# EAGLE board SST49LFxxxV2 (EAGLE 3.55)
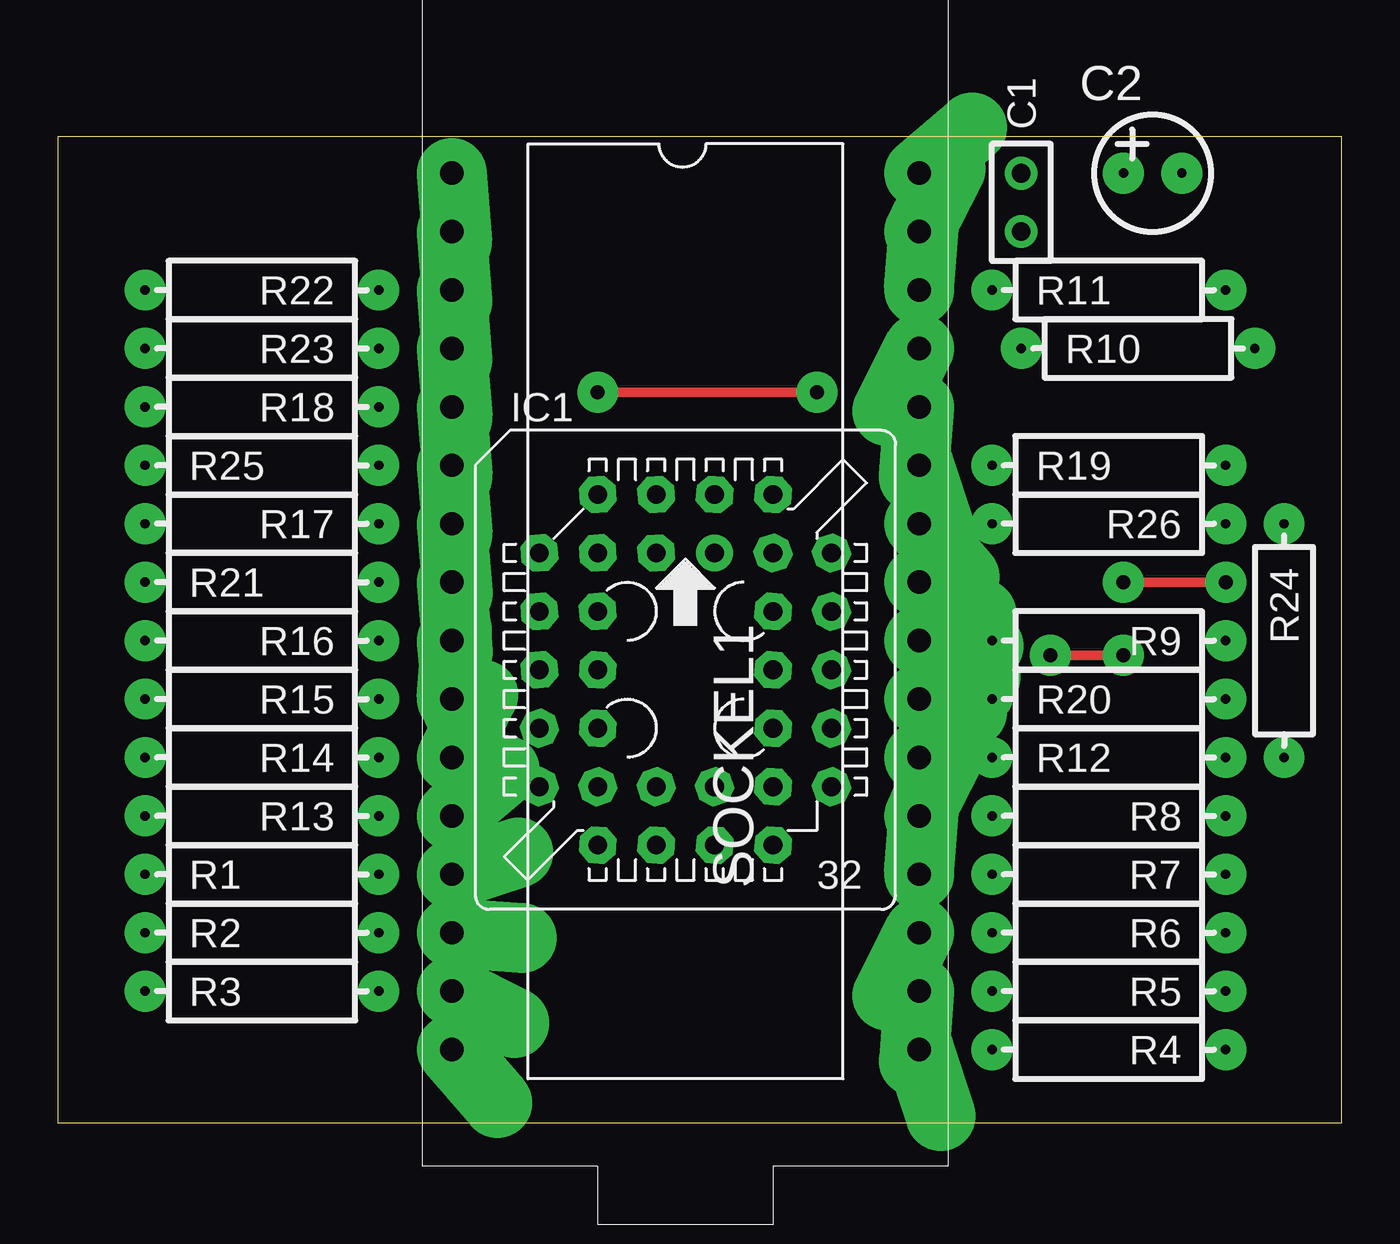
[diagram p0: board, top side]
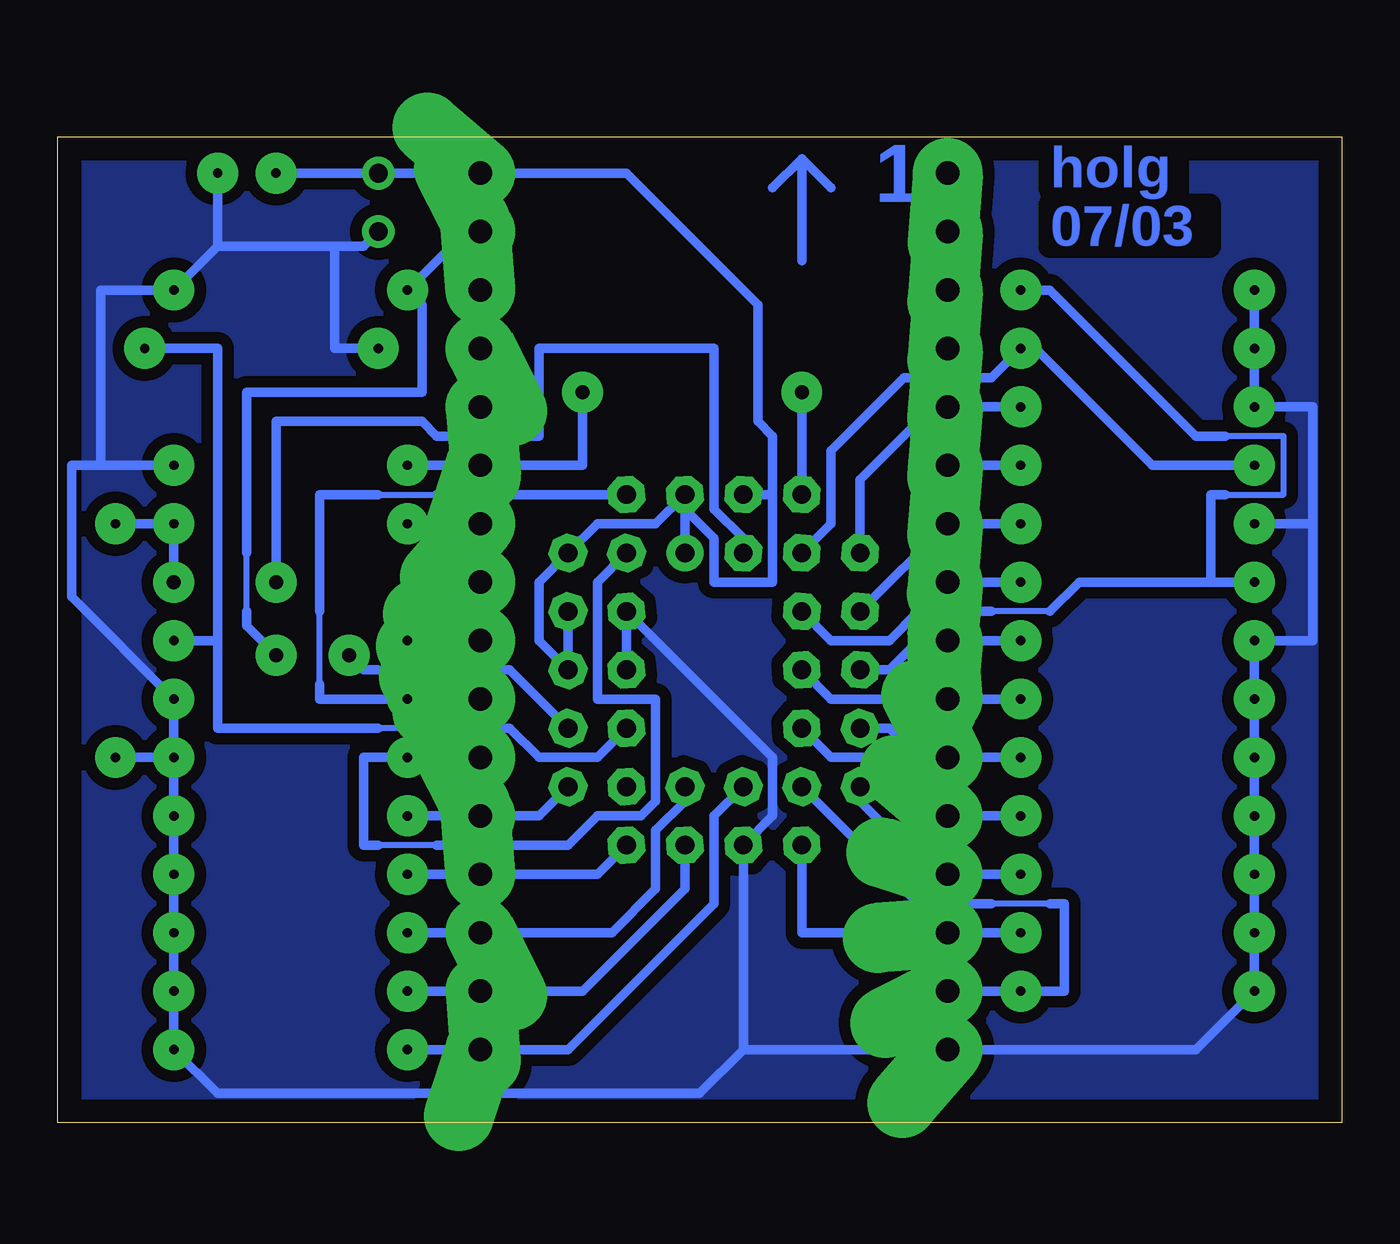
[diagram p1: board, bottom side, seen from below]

Size 55.86 x 42.85 mm. Coordinates in mm from the lower left corner, seen from the top.
Outline: 0,0 55.86,0 55.86,42.85 0,42.85 0,0
Copper layers used: Top, Bottom

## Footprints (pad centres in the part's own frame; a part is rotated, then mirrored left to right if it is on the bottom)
RM2,5 = drill 0.813 pad 1.422 round:  0,0;  2.54,0
KO01 = drill 0.406 pad 1.778 round:  -1.27,0;  1.27,0
C32 = drill 0.813 pad 1.6 round:  1.27,5.08 | drill 0.813 pad 1.6 octagon:  -1.27,7.62;  -1.27,5.08;  -3.81,7.62;  -6.35,5.08;  -3.81,5.08;  -6.35,2.54;  -3.81,2.54;  -6.35,0;  -3.81,0;  -6.35,-2.54;  -3.81,-2.54;  -6.35,-5.08;  -3.81,-7.62;  -3.81,-5.08;  -1.27,-7.62;  -1.27,-5.08;  1.27,-7.62;  1.27,-5.08;  3.81,-7.62;  6.35,-5.08;  3.81,-5.08;  6.35,-2.54;  3.81,-2.54;  6.35,0;  3.81,0;  6.35,2.54;  3.81,2.54;  6.35,5.08;  3.81,7.62;  3.81,5.08;  1.27,7.62
S04 = drill 0.406 pad 1.778 round:  -5.08,0;  5.08,0
AOV32 = drill 1.016 pad 3.048 offset:  -19.05,-10.16;  -16.51,-10.16;  -3.81,-10.16;  -1.27,-10.16;  -13.97,-10.16;  -11.43,-10.16;  -6.35,-10.16;  -8.89,-10.16;  1.27,-10.16;  3.81,-10.16;  6.35,-10.16;  8.89,-10.16;  11.43,-10.16;  13.97,-10.16;  16.51,-10.16;  19.05,-10.16;  19.05,10.16;  16.51,10.16;  13.97,10.16;  11.43,10.16;  8.89,10.16;  6.35,10.16;  3.81,10.16;  1.27,10.16;  -1.27,10.16;  -3.81,10.16;  -6.35,10.16;  -8.89,10.16;  -11.43,10.16;  -13.97,10.16;  -16.51,10.16;  -19.05,10.16

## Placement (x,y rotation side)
C1  C100NK  [RM2,5]  41.91,38.73 90 top
C2  4u7  [KO01]  47.62,41.27 0 top
IC1  SST49LFXXX  [C32]  27.3,19.68 0 top
R1  5k6  [S04]  8.89,10.79 0 top
R2  5k6  [S04]  8.89,8.26 0 top
R3  5k6  [S04]  8.89,5.71 0 top
R4  5k6  [S04]  45.72,3.17 180 top
R5  5k6  [S04]  45.72,5.71 180 top
R6  5k6  [S04]  45.72,8.26 180 top
R7  5k6  [S04]  45.72,10.79 180 top
R8  5k6  [S04]  45.72,13.34 180 top
R9  3k3  [S04]  45.72,20.95 180 top
R10  10k  [S04]  46.99,33.66 0 top
R11  2k7  [S04]  45.72,36.2 0 top
R12  2k7  [S04]  45.72,15.88 0 top
R13  2k7  [S04]  8.89,13.34 180 top
R14  2k7  [S04]  8.89,15.88 180 top
R15  2k7  [S04]  8.89,18.41 180 top
R16  2k7  [S04]  8.89,20.95 180 top
R17  2k7  [S04]  8.89,26.04 180 top
R18  2k7  [S04]  8.89,31.11 180 top
R19  2k7  [S04]  45.72,28.57 0 top
R20  2k7  [S04]  45.72,18.41 0 top
R21  3k3  [S04]  8.89,23.5 0 top
R22  10k  [S04]  8.89,36.2 180 top
R23  10k  [S04]  8.89,33.66 180 top
R24  10k  [S04]  53.34,20.95 270 top
R25  3k3  [S04]  8.89,28.57 0 top
R26  3k3  [S04]  45.72,26.04 180 top
SOCKEL1  Sockel1  [AOV32]  27.3,22.23 270 top

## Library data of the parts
C1 = holgnorm
C2 R1-R26 = holg_plt
IC1 = ic_holg
SOCKEL1 = galeprom

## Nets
/CE: IC1. R12. SOCKEL1.
/OE: R9. SOCKEL1.
/WR: IC1. R11. SOCKEL1.
A0: IC1. R13. SOCKEL1.
A1: IC1. R14. SOCKEL1.
A2: IC1. R15. SOCKEL1.
A3: IC1. R16. SOCKEL1.
A4: R21. SOCKEL1.
A4B: IC1. R21. R22.
A5: IC1. R17. SOCKEL1.
A6: R25. SOCKEL1.
A6B: IC1. R23. R25.
A7: IC1. R18. SOCKEL1.
A8: IC1. R19. SOCKEL1.
A9: R26. SOCKEL1.
A9B: IC1. R24. R26.
A10: IC1. R20. SOCKEL1.
D0: IC1. R1. SOCKEL1.
D1: IC1. R2. SOCKEL1.
D2: IC1. R3. SOCKEL1.
D3: IC1. R4. SOCKEL1.
D4: IC1. R5. SOCKEL1.
D5: IC1. R6. SOCKEL1.
D6: IC1. R7. SOCKEL1.
D7: IC1. R8. SOCKEL1.
GND: C1. C2. IC1. R1. R2. R3. R4. R5. R6. R7. R8. R10. R11. R12. R13. R14. R15. R16. R17. R18. R19. R20. R22. R23. R24. SOCKEL1.
N$1: C1. C2. IC1. SOCKEL1.
N$5: IC1. R9. R10.

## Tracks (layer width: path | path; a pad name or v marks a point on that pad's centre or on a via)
/CE
  Bottom 0.254: 39.37,12.06 41.91,12.06
  Bottom 0.406: 31.11,24.77 32.38,23.5 32.38,18.41 29.84,18.41 29.84,13.97 30.48,13.34 32.38,13.34 33.66,12.06 39.37,12.06 | 37.47,15.88 40.64,15.88 42.55,15.88 42.55,12.06 41.91,12.06
/OE
  Bottom 0.406: 37.47,20.95 R9.
/WR  (via drill 0.61 pad 1.78)
  Top 0.406: v43.18,20.32 v46.35,20.32
  Bottom 0.254: 47.62,22.23 47.62,24.77 | 39.37,19.68 41.91,19.68
  Bottom 0.406: 33.66,17.14 36.2,19.68 39.37,19.68 | v43.18,20.32 42.55,19.68 41.91,19.68 | 37.47,38.73 38.1,38.73 40.64,36.2 40.01,35.56 40.01,31.75 47.62,31.75 47.62,24.77 | 47.62,22.23 47.62,21.59 v46.35,20.32
A0
  Bottom 0.406: 13.97,13.34 17.14,13.34 17.78,13.34 20.32,15.88 22.23,15.88 23.5,17.14
A1
  Bottom 0.406: 13.97,15.88 17.14,15.88 18.41,15.88 19.68,17.14 20.95,17.14
A2
  Bottom 0.406: 23.5,19.68 22.23,18.41 17.14,18.41 13.97,18.41
A3
  Bottom 0.406: 13.97,20.95 17.14,20.95 18.41,20.95 19.68,19.68 20.95,19.68
A4
  Bottom 0.406: R21. 17.14,23.5
A4B
  Bottom 0.254: 5.08,29.84 2.54,29.84 2.54,27.3 5.08,27.3 | 12.7,22.23 15.24,22.23
  Bottom 0.406: 3.81,23.5 5.71,23.5 | 23.5,22.23 22.23,20.95 19.68,20.95 18.41,22.23 15.24,22.23 | 5.71,23.5 11.43,23.5 12.7,22.23 | 5.71,23.5 5.71,27.3 5.08,27.3 | 13.97,36.2 12.7,36.2 6.35,29.84 5.08,29.84
A5
  Bottom 0.406: 20.95,22.23 17.14,26.04 13.97,26.04
A6
  Bottom 0.406: R25. 17.14,28.57
A6B
  Bottom 0.406: 23.5,24.77 22.23,26.04 22.23,29.21 19.05,32.38 15.24,32.38 13.97,33.66 13.34,33.66 8.26,28.57 3.81,28.57
A7
  Bottom 0.406: 20.95,24.77 20.95,27.94 17.78,31.11 17.14,31.11 13.97,31.11
A8  (via drill 0.61 pad 1.78)
  Top 0.406: v23.5,31.75 v33.02,31.75
  Bottom 0.406: 40.64,28.57 37.47,28.57 33.02,28.57 v33.02,31.75 | 23.5,27.3 v23.5,31.75
A9
  Bottom 0.406: 37.47,26.04 R26.
A9B  (via drill 0.61 pad 1.78)
  Top 0.406: v46.35,23.5 v50.8,23.5
  Bottom 0.406: 53.34,26.04 50.8,26.04 v50.8,23.5 | 26.04,24.77 26.04,25.4 27.3,26.67 27.3,33.66 34.92,33.66 34.92,29.84 39.37,29.84 40.01,30.48 46.35,30.48 v46.35,23.5
A10
  Bottom 0.254: 41.91,27.3 39.37,27.3 | 44.45,19.05 44.45,22.23
  Bottom 0.406: 40.64,18.41 37.47,18.41 40.64,18.41 | 40.64,18.41 44.45,18.41 44.45,19.05 | 39.37,27.3 31.11,27.3 | 41.91,27.3 44.45,27.3 44.45,22.23
D0
  Bottom 0.406: R1. 17.14,10.79 17.78,10.79 20.95,13.97 20.95,14.61
D1
  Bottom 0.406: R2. 17.14,8.26 23.5,8.26 23.5,12.06
D2
  Bottom 0.254: 12.7,9.53 15.24,9.53
  Bottom 0.406: 17.14,5.71 R3. 12.06,5.71 12.06,9.53 12.7,9.53 | 23.5,14.61 18.41,9.53 15.24,9.53
D3
  Bottom 0.406: 26.04,14.61 27.3,13.34 27.3,9.53 33.66,3.17 37.47,3.17 R4.
D4
  Bottom 0.406: 28.57,12.06 28.57,10.16 33.02,5.71 37.47,5.71 R5.
D5
  Bottom 0.406: R6. 37.47,8.26 31.75,8.26 29.84,10.16 29.84,12.7 28.57,13.97 28.57,14.61
D6
  Bottom 0.406: 31.11,12.06 32.38,10.79 37.47,10.79 R7.
D7
  Bottom 0.406: 33.66,14.61 34.92,13.34 37.47,13.34 R8.
GND
  Bottom 0.406: 1.27,26.04 1.27,31.11 R18. R23. R22. | 1.27,26.04 R17. | 26.04,3.17 17.14,3.17 6.35,3.17 3.81,5.71 3.81,8.26 3.81,10.79 R13. R14. R15. R16. 1.27,20.95 1.27,26.04 | 26.04,3.17 26.04,12.06 24.77,13.34 24.77,15.88 31.11,22.23 31.11,19.68 | 26.04,3.17 27.94,1.27 48.9,1.27 50.8,3.17 50.8,5.71 50.8,8.26 50.8,10.79 50.8,13.34 R12. | R12. R20. 55.24,22.86 55.24,28.57 53.98,28.57 | 48.9,38.1 R11. 53.98,36.2 53.98,28.57 | 53.98,28.57 R19. | R12. R24. | 48.9,38.1 C2. | 48.9,38.1 43.81,38.1 | 43.81,38.1 42.55,38.1 41.91,38.73 | 41.91,33.66 43.81,33.66 43.81,38.1
  pour Bottom (isolate 0.508): 0.64,41.91 0.64,0.64 55.24,0.64 55.24,41.91
N$1
  Bottom 0.406: 28.57,26.67 IC1. 29.84,26.04 32.38,26.04 33.66,24.77 34.92,23.5 34.92,20.95 33.66,19.68 33.66,22.23 | 28.57,26.67 27.3,25.4 27.3,23.5 24.77,23.5 24.77,27.3 | 24.77,27.3 26.04,27.3 | 24.77,27.3 24.77,29.84 25.4,30.48 25.4,35.56 31.11,41.27 SOCKEL1. C1. 46.35,41.27 | 28.57,26.67 28.57,24.77
N$2
  Bottom 0.406: 23.5,37.47 23.5,41.91 | 23.5,41.91 24.77,40.64 | 23.5,41.91 22.23,40.64
N$5
  Bottom 0.254: 39.37,17.14 41.91,17.14
  Bottom 0.406: 31.11,17.14 32.38,15.88 34.92,15.88 36.2,17.14 39.37,17.14 | 48.9,20.95 50.8,20.95 | 48.9,20.95 48.9,17.14 41.91,17.14 | R10. 48.9,33.66 48.9,20.95

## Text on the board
Bottom: holg | 1 | 07/03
